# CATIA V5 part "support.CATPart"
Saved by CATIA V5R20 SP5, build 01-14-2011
Part number: Part3
Bounding box of the stored display mesh (mm): x -15 to 15, y -40 to 10, z -77.605 to 42.395
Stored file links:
  E:\IAO_2010\iao\IAO_MMS_Groupe2\IAO_MMS_Groupe2\svallart\Assemblage\support.CATPart
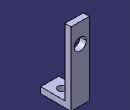
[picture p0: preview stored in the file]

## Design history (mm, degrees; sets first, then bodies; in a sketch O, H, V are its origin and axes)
Body1 (main body)
  Sketch1 on yz-plane, origin (0, 0, 0), H (0, 1, 0), V (0, 0, 1)
    line L1 (0, 42.395) -> (0, -67.605)
    line L2 (0, -67.605) -> (-40, -67.605)
    line L3 (-40, -67.605) -> (-40, -77.605)
    line L4 (-40, -77.605) -> (10, -77.605)
    line L5 (10, -77.605) -> (10, 42.395)
    line L6 (10, 42.395) -> (0, 42.395)
    length L6 = 10
    length L3 = 10
    length L5 = 120
    length L2 = 40
    distance L4 H = 77.605
    vertical: L1 V, L3 V, L5 V
    horizontal: L2 H, L4 H, L6 H
  Pad1: profile Sketch1, direction (1, 0, 0), length 15, mirrored extent
  Sketch2 on face of Pad1 from Sketch1.L2, origin (0, 0, -67.605), H (1, 0, 0), V (0, 1, 0)
    circle A1 centre (0, -20) radius 6.5
    radius A1 = 6.5
  DatumCurve1
  Sketch3 on face of Pad1 from Sketch1.L1, origin (0, 0, 0), H (1, 0, 0), V (0, 0, 1)
    point P1 (0, 10)
    circle A1 centre (0, 10.395) radius 10
    point P2 (0, 10.395)
    reference projected line E1 (-15, 42.395) -> (15, 42.395) from edge [face of Pad1 from Sketch1.L1 | face of Pad1 from Sketch1.L6]
    radius A1 = 10
    distance P2 E1 = 32
  Pocket1: profile Sketch2, direction (0, 0, -1), through (limit type 3)
  Pocket2: profile Sketch3, direction (0, 1, 0), through (limit type 3)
